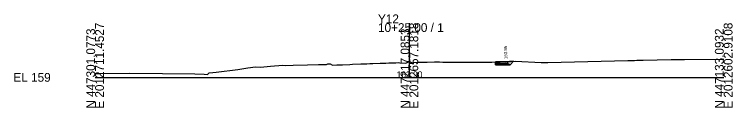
# Model space of a CAD drawing. Extents: x -26 to 1203, y -10 to 9542.
# Drawn here: x -25.7 to 202.8, y 490.3 to 520.1 of the extents above; entities that cross this region are included whole.
import ezdxf

# ---------------------------------------------------------------- set-up
doc = ezdxf.new("R2010")
doc.units = 0
for name, color, linetype in [('Default', 7, 'Continuous'), ('Exist Cross Section Cell', 7, 'Continuous'), ('Exist XS Center Line Elevation Label', 7, 'Continuous'), ('Exist XS Ground Line', 7, 'Continuous'), ('Prop CMT Conc Surface', 7, 'Continuous'), ('Prop CMT Concrete Structures', 7, 'Continuous'), ('Prop CMT Pvmt Course 1', 7, 'Continuous'), ('Prop CMT Pvmt Course 1 CG', 7, 'Continuous'), ('Prop CMT Pvmt Course 2', 7, 'Continuous'), ('Prop CMT Pvmt Course 3', 7, 'Continuous'), ('Prop CMT Pvmt Surface', 7, 'Continuous'), ('Prop CMT Subgrade Earthwork', 7, 'Continuous'), ('Prop XS Earthwork Shape', 7, 'Continuous'), ('Prop XS Hydro Elevations', 7, 'Continuous')]:
    doc.layers.add(name, color=color, linetype=linetype)

msp = doc.modelspace()

# ---------------------------------------------------------------- linework, layer by layer
at = {"layer": 'Exist Cross Section Cell'}
for p, q in [((100, 500), (100, 517.3)), ((0, 500), (100, 500)), ((100, 500), (200, 500))]:
    msp.add_line(p, q, dxfattribs=at)
at = {"layer": 'Exist XS Ground Line'}
msp.add_lwpolyline([(0, 501.21), (1.76, 501.21), (10.98, 501.3), (21.39, 501.28), (31.73, 501.12), (34.74, 501.03), (35.74, 500.93), (36.24, 501.43), (37.41, 501.56), (38.55, 501.64), (45.43, 502.54), (46.05, 502.58), (48.58, 503.05), (51.08, 503.35), (52.59, 503.3), (55.83, 503.54), (59.68, 503.88), (60.57, 503.81), (63.05, 503.91), (67.62, 504.01), (71.03, 504.06), (73.57, 504.15), (74, 504.35), (74.76, 504.32), (75.56, 503.94), (76.96, 503.98), (77.59, 503.99), (78.25, 504.02), (78.68, 504.04), (81.08, 504.15), (81.91, 504.18), (84.56, 504.29), (86.49, 504.36), (87.42, 504.39), (87.89, 504.41), (88.39, 504.43), (90.71, 504.5), (91.08, 504.52), (92.52, 504.57), (93.46, 504.6), (94.33, 504.63), (95.67, 504.68), (96.45, 504.71), (96.91, 504.65), (98.85, 504.53), (99.45, 504.83), (100.29, 504.94), (100.89, 504.63), (101.44, 504.75), (102.42, 504.84), (104.88, 504.86), (105.65, 504.87), (107.98, 504.91), (108.51, 504.91), (109.54, 504.91), (110.64, 504.9), (111.35, 504.9), (114.6, 504.87), (117.27, 504.85), (117.86, 504.85), (118.22, 504.85), (119.01, 504.85), (120.24, 504.86), (123.31, 504.88), (125.07, 504.89), (126.2, 504.9), (127.62, 504.93), (128.24, 504.94), (128.67, 504.93), (129.17, 504.93), (130.54, 504.97), (132.32, 505.09), (133.79, 505.22), (141.91, 504.75), (142.39, 504.75), (142.74, 504.77), (144.08, 504.76), (169.52, 505.37), (171.66, 505.43), (172.39, 505.45), (172.95, 505.45), (174.4, 505.45), (183.31, 505.67), (187.51, 505.75), (198.86, 505.76), (200, 505.77)], dxfattribs=at)
at = {"layer": 'Prop CMT Conc Surface'}
msp.add_lwpolyline([(128.68, 504.93), (130.69, 504.86)], dxfattribs=at)
at = {"layer": 'Prop CMT Concrete Structures'}
for p, q in [((131.18, 504.98), (133.15, 505.16)), ((130.69, 504.86), (131.18, 504.98))]:
    msp.add_line(p, q, dxfattribs=at)
for points in [[(131.18, 504.98), (131.2, 504.36), (128.68, 504.34)], [(128.68, 504.34), (128.68, 504.93)]]:
    msp.add_lwpolyline(points, dxfattribs=at)
at = {"layer": 'Prop CMT Pvmt Course 1'}
for points in [[(127.41, 504.92), (128.68, 504.93)], [(127.41, 504.92), (127.41, 504.92)], [(127.41, 504.67), (127.41, 504.92)], [(128.68, 504.68), (127.41, 504.67)], [(128.68, 504.93), (128.68, 504.68)]]:
    msp.add_lwpolyline(points, dxfattribs=at)
at = {"layer": 'Prop CMT Pvmt Course 1 CG'}
for points in [[(128.68, 504.34), (131.68, 504.36), (132.02, 504.03)], [(128.68, 504.01), (128.68, 504.34)], [(132.02, 504.03), (128.68, 504.01)]]:
    msp.add_lwpolyline(points, dxfattribs=at)
at = {"layer": 'Prop CMT Pvmt Course 2'}
for points in [[(127.41, 504.67), (128.68, 504.68)], [(127.41, 504.34), (127.41, 504.67)], [(128.68, 504.34), (127.41, 504.34)], [(128.68, 504.68), (128.68, 504.34)]]:
    msp.add_lwpolyline(points, dxfattribs=at)
at = {"layer": 'Prop CMT Pvmt Course 3'}
for points in [[(127.41, 504.34), (128.68, 504.34)], [(127.41, 504), (127.41, 504.34)], [(128.68, 504.01), (127.41, 504)], [(128.68, 504.34), (128.68, 504.01)]]:
    msp.add_lwpolyline(points, dxfattribs=at)
at = {"layer": 'Prop CMT Pvmt Surface'}
msp.add_lwpolyline([(127.41, 504.92), (128.68, 504.93)], dxfattribs=at)
at = {"layer": 'Prop CMT Subgrade Earthwork'}
for points in [[(128.68, 504.01), (132.02, 504.03), (133.15, 505.16)], [(127.41, 504), (127.41, 504.92)], [(127.41, 504), (128.68, 504.01)], [(128.68, 504.01), (127.41, 504)]]:
    msp.add_lwpolyline(points, dxfattribs=at)
at = {"layer": 'Prop XS Earthwork Shape'}
msp.add_lwpolyline([(127.41, 504.92), (127.41, 504), (132.02, 504.03), (133.15, 505.16), (130.54, 504.97)], close=True, dxfattribs=at)

# ---------------------------------------------------------------- texts
at = {"layer": 'Default'}
msp.add_text('-', height=0.0001, dxfattribs=at).set_placement((0, 500))
at = {"layer": 'Exist Cross Section Cell'}
for s, p in [('Y12', (90, 517.3)), ('10+25.00 / 1', (90, 514.5)), ('EL 159', (-26, 498.6))]:
    msp.add_text(s, height=2.8, dxfattribs=at).set_placement(p)
for s, p in [('E 2012711.4527', (2.8, 490)), ('E 2012657.1818', (102.8, 490)), ('E 2012602.9108', (202.8, 490)), ('N 447301.0773', (0, 490)), ('N 447217.0853', (100, 490)), ('N 447133.0932', (200, 490))]:
    msp.add_text(s, height=2.8, rotation=90, dxfattribs=at).set_placement(p)
at = {"layer": 'Exist XS Center Line Elevation Label'}
msp.add_text('163.90', height=2, dxfattribs=at).set_placement((95.95, 499.9))
at = {"layer": 'Prop XS Hydro Elevations'}
msp.add_text('163.86', height=1, rotation=91.7179, dxfattribs=at).set_placement((131.16, 505.87))

doc.saveas('drawing.dxf')
